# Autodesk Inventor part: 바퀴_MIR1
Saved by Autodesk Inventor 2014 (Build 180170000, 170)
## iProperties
Created: 2015-05
Part Number: 바퀴_MIR1
Material: 일반
Vendor: CBT Solutions
Document SubType Name: 모델링
Designer: Administrator
Appearance: 기본값
Company: 한국ATC센터
Author: KYOUNG IL JANG
Comments: 파생
d0: 1.000 ul
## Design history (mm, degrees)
derived "바퀴.ipt" dims count "d0" = 1
feature "솔리드1::바퀴.ipt" dims count "d0" = 1
tag "피쳐 태그1"
node "솔리드1"
